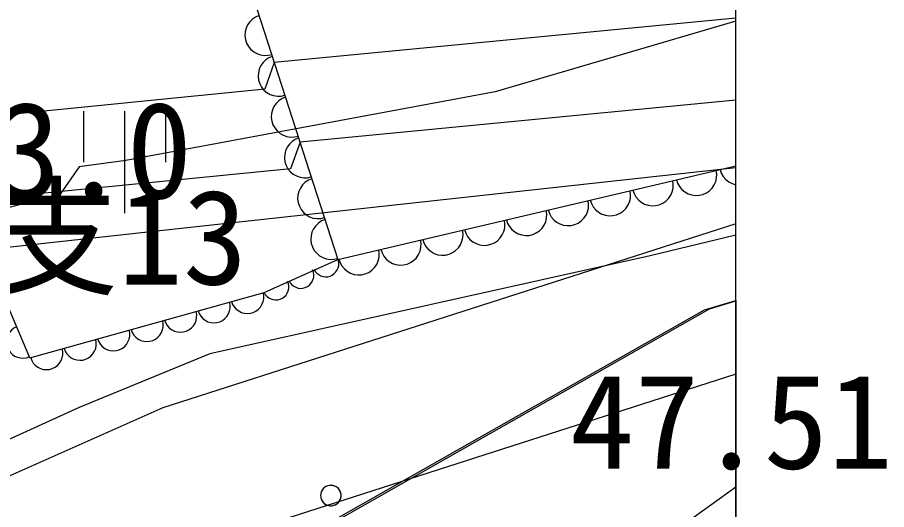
# Model space of a CAD drawing. Extents: x 42655 to 43811, y -141820 to -141156.
# Drawn here: x 43677.04 to 43687.67, y -141340.51 to -141334.49 of the extents above; entities that cross this region are included whole.
import ezdxf

# ---------------------------------------------------------------- set-up
doc = ezdxf.new("R2010")
doc.units = 0
for name, color, linetype in [('D-TTL', 7, 'Continuous'), ('ZE_LWCN', 7, 'Continuous'), ('地形', 7, 'Continuous'), ('現況道路ﾊｯﾁ', 7, 'Continuous')]:
    doc.layers.add(name, color=color, linetype=linetype)

msp = doc.modelspace()

# ---------------------------------------------------------------- linework, layer by layer
at = {"layer": 'D-TTL'}
msp.add_lwpolyline([(42724.63, -141820.399), (43685.83, -141820.386), (43685.821, -141155.586), (42724.621, -141155.599), (42724.63, -141820.399)], dxfattribs=at)
at = {"layer": 'ZE_LWCN'}
for points in [[(43685.824, -141334.534), (43682.882, -141335.398), (43678.368, -141336.238), (43677.798, -141336.315), (43677.566, -141336.65), (43676.457, -141336.938), (43672.722, -141338.79), (43670.156, -141340.015), (43667.636, -141339.291)], [(43685.824, -141340.231), (43684.399, -141341.259), (43682.914, -141342.097), (43682.292, -141342.318), (43679.705, -141343.085), (43678.117, -141343.438), (43677.837, -141344.532), (43677.556, -141343.43), (43672.744, -141343.497), (43672.041, -141343.121), (43667.648, -141341.858)]]:
    msp.add_lwpolyline(points, dxfattribs=at)
at = {"layer": '地形'}
for p, q in [((43685.824, -141334.497), (43680.184, -141335.041)), ((43680.184, -141335.041), (43680.068, -141335.365)), ((43680.068, -141335.366), (43675.978, -141335.772)), ((43685.824, -141335.502), (43680.499, -141336.015)), ((43677.854, -141335.633), (43677.854, -141336.258)), ((43678.354, -141335.633), (43678.354, -141336.883)), ((43678.854, -141335.633), (43678.854, -141336.258)), ((43680.499, -141336.015), (43680.382, -141336.339)), ((43680.382, -141336.339), (43676.386, -141336.737)), ((43685.824, -141336.327), (43676.851, -141337.311)), ((43685.824, -141337.01), (43678.82, -141339.262)), ((43685.824, -141338.848), (43679.355, -141340.928))]:
    msp.add_line(p, q, dxfattribs=at)
for points in [[(43677.195, -141338.652), (43675.862, -141335.497), (43672.911, -141336.064), (43671.259, -141331.064), (43669.107, -141327.164)], [(43679.673, -141333.457), (43680.961, -141337.446), (43684.543, -141336.604), (43685.824, -141336.301)], [(43679.998, -141334.466), (43679.956, -141334.484), (43679.918, -141334.51), (43679.885, -141334.542), (43679.858, -141334.58), (43679.839, -141334.622), (43679.828, -141334.666), (43679.825, -141334.713), (43679.831, -141334.758), (43679.845, -141334.802), (43679.867, -141334.843), (43679.896, -141334.879), (43679.932, -141334.908), (43679.972, -141334.931), (43680.015, -141334.946), (43680.061, -141334.953), (43680.107, -141334.952), (43680.152, -141334.942)], [(43680.159, -141334.965), (43680.117, -141334.983), (43680.079, -141335.008), (43680.046, -141335.041), (43680.019, -141335.078), (43680, -141335.12), (43679.989, -141335.165), (43679.986, -141335.211), (43679.992, -141335.257), (43680.006, -141335.301), (43680.028, -141335.341), (43680.057, -141335.377), (43680.093, -141335.407), (43680.133, -141335.43), (43680.176, -141335.445), (43680.222, -141335.452), (43680.268, -141335.45), (43680.313, -141335.44)], [(43680.32, -141335.463), (43680.278, -141335.481), (43680.24, -141335.507), (43680.207, -141335.539), (43680.18, -141335.577), (43680.161, -141335.619), (43680.15, -141335.664), (43680.147, -141335.71), (43680.153, -141335.756), (43680.167, -141335.8), (43680.189, -141335.84), (43680.219, -141335.876), (43680.254, -141335.906), (43680.294, -141335.929), (43680.337, -141335.944), (43680.383, -141335.951), (43680.429, -141335.949), (43680.474, -141335.939)], [(43680.481, -141335.962), (43680.439, -141335.98), (43680.401, -141336.006), (43680.368, -141336.038), (43680.341, -141336.076), (43680.322, -141336.118), (43680.311, -141336.162), (43680.308, -141336.208), (43680.314, -141336.254), (43680.328, -141336.298), (43680.35, -141336.339), (43680.38, -141336.375), (43680.415, -141336.404), (43680.455, -141336.427), (43680.498, -141336.442), (43680.544, -141336.449), (43680.59, -141336.448), (43680.635, -141336.438)], [(43685.098, -141336.473), (43685.113, -141336.516), (43685.136, -141336.557), (43685.165, -141336.592), (43685.201, -141336.622), (43685.241, -141336.644), (43685.285, -141336.659), (43685.331, -141336.665), (43685.377, -141336.663), (43685.421, -141336.652), (43685.464, -141336.633), (43685.502, -141336.607), (43685.534, -141336.575), (43685.56, -141336.537), (43685.579, -141336.494), (43685.589, -141336.449), (43685.591, -141336.403), (43685.585, -141336.358)], [(43685.631, -141336.347), (43685.646, -141336.392), (43685.669, -141336.433), (43685.7, -141336.469), (43685.737, -141336.498), (43685.779, -141336.52), (43685.824, -141336.534)], [(43680.642, -141336.46), (43680.6, -141336.479), (43680.562, -141336.504), (43680.529, -141336.537), (43680.502, -141336.574), (43680.483, -141336.616), (43680.472, -141336.661), (43680.469, -141336.707), (43680.475, -141336.753), (43680.49, -141336.797), (43680.512, -141336.837), (43680.541, -141336.873), (43680.576, -141336.903), (43680.616, -141336.926), (43680.659, -141336.941), (43680.705, -141336.948), (43680.751, -141336.946), (43680.796, -141336.936)], [(43684.566, -141336.599), (43684.581, -141336.642), (43684.603, -141336.683), (43684.633, -141336.718), (43684.668, -141336.748), (43684.709, -141336.77), (43684.752, -141336.785), (43684.798, -141336.791), (43684.844, -141336.789), (43684.889, -141336.778), (43684.931, -141336.759), (43684.969, -141336.733), (43685.002, -141336.701), (43685.028, -141336.663), (43685.047, -141336.62), (43685.057, -141336.575), (43685.059, -141336.529), (43685.053, -141336.484)], [(43684.044, -141336.722), (43684.059, -141336.765), (43684.081, -141336.806), (43684.111, -141336.841), (43684.146, -141336.871), (43684.186, -141336.893), (43684.23, -141336.908), (43684.276, -141336.914), (43684.322, -141336.912), (43684.367, -141336.901), (43684.409, -141336.883), (43684.447, -141336.857), (43684.48, -141336.824), (43684.506, -141336.786), (43684.524, -141336.744), (43684.535, -141336.699), (43684.537, -141336.653), (43684.531, -141336.607)], [(43683.532, -141336.842), (43683.547, -141336.886), (43683.569, -141336.926), (43683.599, -141336.961), (43683.634, -141336.991), (43683.675, -141337.013), (43683.718, -141337.028), (43683.764, -141337.034), (43683.81, -141337.032), (43683.855, -141337.022), (43683.897, -141337.003), (43683.935, -141336.977), (43683.968, -141336.944), (43683.994, -141336.906), (43684.013, -141336.864), (43684.023, -141336.819), (43684.025, -141336.773), (43684.019, -141336.727)], [(43683.02, -141336.962), (43683.035, -141337.006), (43683.058, -141337.046), (43683.087, -141337.082), (43683.122, -141337.111), (43683.163, -141337.134), (43683.207, -141337.148), (43683.252, -141337.155), (43683.298, -141337.153), (43683.343, -141337.142), (43683.385, -141337.123), (43683.423, -141337.097), (43683.456, -141337.065), (43683.482, -141337.027), (43683.501, -141336.984), (43683.511, -141336.939), (43683.514, -141336.893), (43683.507, -141336.848)], [(43680.804, -141336.959), (43680.761, -141336.977), (43680.723, -141337.003), (43680.69, -141337.035), (43680.663, -141337.073), (43680.644, -141337.115), (43680.633, -141337.16), (43680.63, -141337.206), (43680.636, -141337.252), (43680.651, -141337.295), (43680.673, -141337.336), (43680.702, -141337.372), (43680.737, -141337.402), (43680.777, -141337.425), (43680.82, -141337.44), (43680.866, -141337.447), (43680.912, -141337.445), (43680.957, -141337.435)], [(43682.509, -141337.082), (43682.523, -141337.126), (43682.546, -141337.166), (43682.575, -141337.202), (43682.611, -141337.231), (43682.651, -141337.254), (43682.695, -141337.269), (43682.74, -141337.275), (43682.787, -141337.273), (43682.831, -141337.262), (43682.874, -141337.244), (43682.912, -141337.218), (43682.944, -141337.185), (43682.97, -141337.147), (43682.989, -141337.105), (43683, -141337.06), (43683.002, -141337.014), (43682.995, -141336.968)], [(43685.824, -141337.149), (43684.779, -141337.405), (43679.398, -141338.6), (43677.8, -141339.256), (43676.052, -141340.05), (43674.167, -141341.209), (43674.345, -141341.538), (43673.401, -141342.094), (43673.304, -141341.965), (43670.476, -141343.376)], [(43681.997, -141337.203), (43682.012, -141337.246), (43682.034, -141337.287), (43682.063, -141337.322), (43682.099, -141337.352), (43682.139, -141337.374), (43682.183, -141337.389), (43682.229, -141337.395), (43682.275, -141337.393), (43682.32, -141337.383), (43682.362, -141337.364), (43682.4, -141337.338), (43682.433, -141337.305), (43682.459, -141337.267), (43682.477, -141337.225), (43682.488, -141337.18), (43682.49, -141337.134), (43682.484, -141337.088)], [(43681.485, -141337.323), (43681.5, -141337.367), (43681.522, -141337.407), (43681.552, -141337.443), (43681.587, -141337.472), (43681.627, -141337.495), (43681.671, -141337.509), (43681.717, -141337.516), (43681.763, -141337.513), (43681.808, -141337.503), (43681.85, -141337.484), (43681.888, -141337.458), (43681.921, -141337.426), (43681.947, -141337.388), (43681.966, -141337.345), (43681.976, -141337.3), (43681.978, -141337.254), (43681.972, -141337.209)], [(43680.973, -141337.443), (43680.988, -141337.487), (43681.01, -141337.527), (43681.04, -141337.563), (43681.075, -141337.592), (43681.116, -141337.615), (43681.159, -141337.63), (43681.205, -141337.636), (43681.251, -141337.634), (43681.296, -141337.623), (43681.338, -141337.605), (43681.376, -141337.579), (43681.409, -141337.546), (43681.435, -141337.508), (43681.454, -141337.466), (43681.464, -141337.421), (43681.466, -141337.375), (43681.46, -141337.329)], [(43677.195, -141338.652), (43680.059, -141337.85), (43680.961, -141337.446)], [(43680.67, -141337.568), (43680.685, -141337.593), (43680.704, -141337.615), (43680.726, -141337.633), (43680.752, -141337.647), (43680.78, -141337.656), (43680.809, -141337.66), (43680.838, -141337.658), (43680.866, -141337.651), (43680.893, -141337.638), (43680.917, -141337.621), (43680.937, -141337.6), (43680.953, -141337.576), (43680.964, -141337.549), (43680.971, -141337.52), (43680.971, -141337.491), (43680.967, -141337.462), (43680.957, -141337.435)], [(43680.365, -141337.709), (43680.379, -141337.734), (43680.398, -141337.756), (43680.421, -141337.775), (43680.447, -141337.788), (43680.475, -141337.797), (43680.504, -141337.801), (43680.533, -141337.799), (43680.561, -141337.792), (43680.588, -141337.779), (43680.612, -141337.762), (43680.632, -141337.741), (43680.648, -141337.717), (43680.659, -141337.69), (43680.665, -141337.662), (43680.666, -141337.632), (43680.662, -141337.604), (43680.652, -141337.576)], [(43680.059, -141337.85), (43680.074, -141337.875), (43680.093, -141337.898), (43680.116, -141337.916), (43680.142, -141337.93), (43680.17, -141337.938), (43680.199, -141337.942), (43680.228, -141337.94), (43680.256, -141337.933), (43680.282, -141337.921), (43680.306, -141337.904), (43680.327, -141337.883), (43680.343, -141337.858), (43680.354, -141337.831), (43680.36, -141337.803), (43680.361, -141337.774), (43680.356, -141337.745), (43680.347, -141337.717)], [(43679.662, -141337.961), (43679.675, -141337.996), (43679.695, -141338.027), (43679.719, -141338.055), (43679.749, -141338.077), (43679.782, -141338.094), (43679.817, -141338.104), (43679.854, -141338.107), (43679.891, -141338.104), (43679.926, -141338.094), (43679.959, -141338.078), (43679.989, -141338.056), (43680.014, -141338.029), (43680.033, -141337.997), (43680.047, -141337.963), (43680.054, -141337.927), (43680.054, -141337.89), (43680.047, -141337.853)], [(43611.781, -141345.207), (43621.483, -141345.458), (43626.083, -141345.458), (43631.017, -141345.625), (43633.945, -141345.29), (43638.545, -141344.705), (43647.107, -141343.483), (43653.133, -141342.421), (43659.63, -141342.657), (43666.601, -141343.483), (43672.39, -141343.247), (43676.17, -141342.42), (43680.305, -141341.004), (43685.503, -141338.052), (43685.824, -141337.954)], [(43679.253, -141338.076), (43679.266, -141338.11), (43679.285, -141338.142), (43679.31, -141338.169), (43679.34, -141338.191), (43679.372, -141338.208), (43679.408, -141338.218), (43679.445, -141338.222), (43679.481, -141338.219), (43679.517, -141338.209), (43679.55, -141338.192), (43679.58, -141338.17), (43679.605, -141338.143), (43679.624, -141338.112), (43679.638, -141338.077), (43679.645, -141338.041), (43679.645, -141338.004), (43679.638, -141337.968)], [(43678.844, -141338.19), (43678.857, -141338.225), (43678.876, -141338.256), (43678.901, -141338.284), (43678.93, -141338.306), (43678.963, -141338.323), (43678.999, -141338.333), (43679.035, -141338.336), (43679.072, -141338.333), (43679.108, -141338.323), (43679.141, -141338.307), (43679.17, -141338.285), (43679.195, -141338.258), (43679.215, -141338.226), (43679.228, -141338.192), (43679.235, -141338.156), (43679.236, -141338.119), (43679.229, -141338.082)], [(43678.434, -141338.305), (43678.448, -141338.339), (43678.467, -141338.371), (43678.492, -141338.398), (43678.521, -141338.42), (43678.554, -141338.437), (43678.589, -141338.447), (43678.626, -141338.451), (43678.663, -141338.448), (43678.699, -141338.438), (43678.732, -141338.421), (43678.761, -141338.399), (43678.786, -141338.372), (43678.806, -141338.341), (43678.819, -141338.306), (43678.826, -141338.27), (43678.826, -141338.233), (43678.82, -141338.197)], [(43677.034, -141338.27), (43677.001, -141338.288), (43676.972, -141338.311), (43676.948, -141338.339), (43676.93, -141338.371), (43676.918, -141338.406), (43676.912, -141338.442), (43676.913, -141338.479), (43676.921, -141338.515), (43676.935, -141338.549), (43676.956, -141338.58), (43676.981, -141338.606), (43677.011, -141338.628), (43677.045, -141338.643), (43677.081, -141338.652), (43677.117, -141338.654), (43677.154, -141338.65), (43677.189, -141338.639)], [(43678.025, -141338.419), (43678.038, -141338.454), (43678.058, -141338.485), (43678.082, -141338.513), (43678.112, -141338.535), (43678.145, -141338.552), (43678.18, -141338.562), (43678.217, -141338.565), (43678.254, -141338.562), (43678.289, -141338.552), (43678.322, -141338.536), (43678.352, -141338.514), (43678.377, -141338.487), (43678.396, -141338.455), (43678.41, -141338.421), (43678.417, -141338.385), (43678.417, -141338.348), (43678.41, -141338.312)], [(43677.616, -141338.534), (43677.629, -141338.568), (43677.648, -141338.6), (43677.673, -141338.627), (43677.703, -141338.649), (43677.736, -141338.666), (43677.771, -141338.676), (43677.808, -141338.68), (43677.844, -141338.677), (43677.88, -141338.667), (43677.913, -141338.65), (43677.943, -141338.628), (43677.968, -141338.601), (43677.987, -141338.57), (43678.001, -141338.535), (43678.008, -141338.499), (43678.008, -141338.462), (43678.001, -141338.426)], [(43677.207, -141338.648), (43677.22, -141338.683), (43677.239, -141338.714), (43677.264, -141338.742), (43677.293, -141338.764), (43677.326, -141338.781), (43677.362, -141338.791), (43677.398, -141338.794), (43677.435, -141338.791), (43677.471, -141338.781), (43677.504, -141338.765), (43677.533, -141338.743), (43677.558, -141338.716), (43677.578, -141338.684), (43677.591, -141338.65), (43677.598, -141338.614), (43677.599, -141338.577), (43677.592, -141338.541)], [(43678.82, -141339.262), (43675.555, -141340.711), (43672.672, -141342.82), (43670.302, -141345.492)], [(43680.749, -141340.333), (43680.751, -141340.356), (43680.757, -141340.377), (43680.767, -141340.397), (43680.78, -141340.415), (43680.796, -141340.431), (43680.815, -141340.443), (43680.836, -141340.452), (43680.857, -141340.457), (43680.88, -141340.458), (43680.902, -141340.455), (43680.923, -141340.448), (43680.943, -141340.438), (43680.961, -141340.424), (43680.975, -141340.407), (43680.987, -141340.387), (43680.995, -141340.366), (43680.999, -141340.344), (43680.999, -141340.322), (43680.995, -141340.3), (43680.987, -141340.279), (43680.975, -141340.26), (43680.961, -141340.243), (43680.943, -141340.229), (43680.923, -141340.218), (43680.902, -141340.211), (43680.88, -141340.208), (43680.857, -141340.209), (43680.836, -141340.214), (43680.815, -141340.223), (43680.796, -141340.235), (43680.78, -141340.251), (43680.767, -141340.269), (43680.757, -141340.289), (43680.751, -141340.311), (43680.749, -141340.333)], [(43680.999, -141340.333), (43680.997, -141340.31), (43680.991, -141340.288), (43680.981, -141340.267), (43680.967, -141340.249), (43680.95, -141340.233), (43680.93, -141340.221), (43680.908, -141340.213), (43680.886, -141340.209), (43680.863, -141340.209), (43680.84, -141340.213), (43680.819, -141340.221), (43680.799, -141340.233), (43680.782, -141340.249), (43680.768, -141340.267), (43680.758, -141340.288), (43680.751, -141340.31), (43680.749, -141340.333)], [(43680.749, -141340.333), (43680.751, -141340.356), (43680.758, -141340.378), (43680.768, -141340.399), (43680.782, -141340.417), (43680.799, -141340.433), (43680.819, -141340.445), (43680.84, -141340.453), (43680.863, -141340.458), (43680.886, -141340.458), (43680.908, -141340.453), (43680.93, -141340.445), (43680.95, -141340.433), (43680.967, -141340.417), (43680.981, -141340.399), (43680.991, -141340.378), (43680.997, -141340.356), (43680.999, -141340.333)]]:
    msp.add_lwpolyline(points, dxfattribs=at)
at = {"layer": '現況道路ﾊｯﾁ'}
msp.add_lwpolyline([(43670.133, -141369.045), (43670.051, -141365.122), (43669.847, -141359.862), (43669.804, -141358.275), (43670.051, -141355.52), (43670.95, -141351.434), (43671.768, -141347.675), (43672.39, -141343.247), (43676.11, -141342.432), (43680.245, -141341.015), (43685.443, -141338.064), (43685.824, -141337.948), (43685.824, -141342.398), (43685.325, -141342.786), (43684.971, -141343.495), (43685.824, -141343.665), (43685.824, -141348.013), (43679.026, -141347.283), (43677.326, -141347.519), (43675.324, -141352.521), (43674.466, -141361.812), (43675.038, -141369.102)], dxfattribs=at)

# ---------------------------------------------------------------- texts
at = {"layer": '地形'}
for s, height, p in [('E縄地213.0', 1.1799, (43671.297, -141336.7)), ('NTT上条支13', 1.1606, (43671.382, -141337.754)), ('47.51', 1.1606, (43683.795, -141340.006))]:
    msp.add_text(s, height=height, dxfattribs=at).set_placement(p)

doc.saveas('drawing.dxf')
